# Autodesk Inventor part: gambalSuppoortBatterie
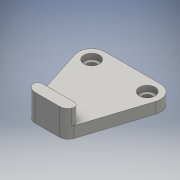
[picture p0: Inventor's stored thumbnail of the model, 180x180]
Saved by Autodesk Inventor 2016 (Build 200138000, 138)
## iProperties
Created: 2016-01
Part Number: gambalSuppoortBatterie
Material: Generic
Document SubType Name: Modeling
Designer: Peter
Density: 1 g/cm^3
Appearance: Default
Author: Peter
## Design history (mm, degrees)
sketch "Esquisse1"
  geometry: L1 (-12.5, 0)-(12.5, 0); L2 (-12.5, 6)-(12.5, 6); L3 (-10, -27.5)-(10, -27.5); L4 (0, 0)-(0, -32.5); L5 (-5.48, -32.5)-(5.48, -32.5); L6 (-18.215, -1.829)-(-9.29, -29.719); L7 (9.29, -29.719)-(18.215, -1.829); C1 r 2 at (-12.5, 0); C2 r 2 at (12.5, 0); A1 r 6 centre (-12.5, 0) between (-12.5, 6) and (-18.215, -1.829); A2 r 6 centre (12.5, 0) between (18.215, -1.829) and (12.5, 6); A3 r 4 centre (-5.48, -28.5) between (-9.29, -29.719) and (-5.48, -32.5); A4 r 4 centre (5.48, -28.5) between (5.48, -32.5) and (9.29, -29.719); 2 further points
  constraints: 14 end point, 10 point on circle, 8 tangent, 6 centre point, 5 coincident, 5 point on line, 3 equal radius, 3 midpoint, 1 horizontal, 1 parallel, 1 vertical
  dimensions: "d0" = 25 distance of L1.start L1.end; "d1" = 4 diameter of C1; "d2" = 4 radial gap between concentric circles of A1 C1; "d3" = 27.5 distance between parallel lines of L3 L1; "d5" = 5 distance between parallel lines of L3 L5; "d10" = 20 distance of L3.start L3.end; "d11" = 4 radius of A4
extrude "Extrusion1" new body sketch "Esquisse1" distance "d8" = 5; taper "d9" = 0 deg
sketch "Esquisse2"
  geometry: L1 (-10, -27.5)-(10, -27.5); L2 (-5.48, -32.5)-(5.48, -32.5) reference; L3 (-18.215, -1.829)-(-9.29, -29.719) reference; L4 (9.29, -29.719)-(18.215, -1.829) reference; A1 r 4 centre (-5.48, -28.5) between (-9.29, -29.719) and (-5.48, -32.5) reference; A2 r 4 centre (5.48, -28.5) between (5.48, -32.5) and (9.29, -29.719) reference; 1 further point
  constraints: 2 end point, 2 point on line, 1 parallel
  dimensions: "d12" = 5 distance between parallel lines of L1 L2
extrude "Extrusion2" join sketch "Esquisse2" distance "d13" = 7; taper "d14" = 0 deg
fillet "Congé1" dims "d15" = 2
sketch "Esquisse3"
  geometry: C1 r 3.5 at (12.5, 0); C2 r 3.5 at (-12.5, 0); C3 r 2 at (12.5, 0) reference; C4 r 2 at (-12.5, 0) reference; 1 further point
  constraints: 2 centre point, 2 concentric, 1 equal radius
  dimensions: "d16" = 7 diameter of C1
extrude "Extrusion3" cut sketch "Esquisse3" distance "d17" = 2.5; taper "d18" = 0 deg
node "Solide1"
